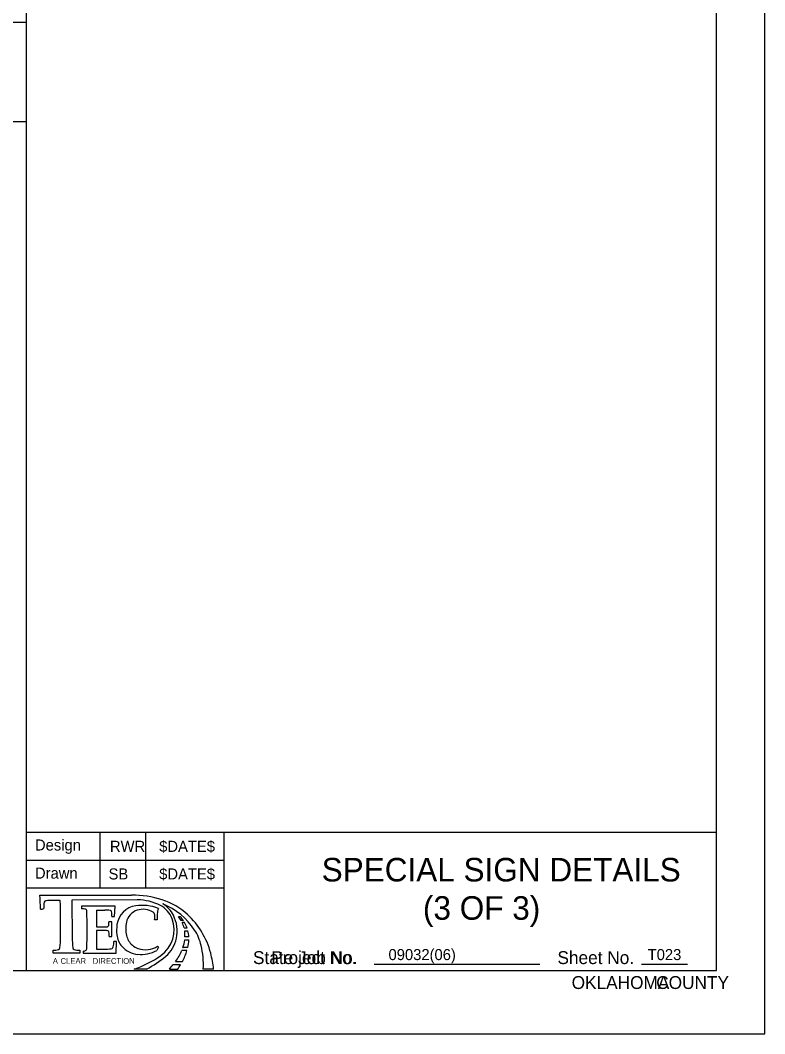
# Model space of a CAD drawing. Extents: x 2150010 to 2150174, y 145114 to 145224.
# Drawn here: x 2150135.1 to 2150174.1, y 145114.1 to 145167.1 of the extents above; entities that cross this region are included whole.
import ezdxf

# ---------------------------------------------------------------- set-up
doc = ezdxf.new("R2010")
doc.units = 0
for name, color, linetype in [('BORDER', 7, 'Continuous'), ('DATE', 7, 'Continuous'), ('Level 1', 7, 'Continuous'), ('PDF', 7, 'Continuous'), ('project no', 7, 'Continuous'), ('state job no', 7, 'Continuous'), ('TEC LOGO', 7, 'Continuous'), ('TEXT', 7, 'Continuous')]:
    doc.layers.add(name, color=color, linetype=linetype)

msp = doc.modelspace()

# ---------------------------------------------------------------- linework, layer by layer
at = {"layer": 'BORDER'}
for p, q in [((2150171.536, 145117.388), (2150171.536, 145216.512)), ((2150171.536, 145124.606), (2150135.447, 145124.606)), ((2150135.447, 145124.606), (2150135.447, 145117.388)), ((2150139.297, 145124.606), (2150139.297, 145121.719)), ((2150141.703, 145121.719), (2150141.703, 145124.606)), ((2150145.8, 145117.359), (2150145.8, 145124.577)), ((2150135.447, 145123.162), (2150145.8, 145123.162)), ((2150135.447, 145121.719), (2150145.8, 145121.719)), ((2150153.637, 145117.729), (2150162.298, 145117.729)), ((2150167.618, 145117.729), (2150170.024, 145117.729)), ((2150017.557, 145117.388), (2150171.536, 145117.388)), ((2150171.536, 145117.388), (2150171.536, 145117.388)), ((2150010.458, 145114.088), (2150174.061, 145114.088))]:
    msp.add_line(p, q, dxfattribs=at)
at = {"layer": 'Level 1'}
for p, q in [((2150135.447, 145216.512), (2150135.447, 145124.606)), ((2150135.447, 145166.95), (2150017.557, 145166.95)), ((2150120.969, 145161.778), (2150135.447, 145161.778))]:
    msp.add_line(p, q, dxfattribs=at)
at = {"layer": 'PDF'}
msp.add_lwpolyline([(2150010.458, 145114.088), (2150174.061, 145114.088), (2150174.061, 145219.948), (2150010.458, 145219.948)], close=True, dxfattribs=at)
at = {"layer": 'TEC LOGO'}
for p, q in [((2150136.163, 145121.335), (2150140.955, 145121.335)), ((2150137.238, 145121.058), (2150136.905, 145121.056)), ((2150141.264, 145121.082), (2150137.847, 145121.062)), ((2150137.847, 145121.062), (2150137.86, 145119.111)), ((2150138.352, 145120.759), (2150138.349, 145120.611)), ((2150140.106, 145120.759), (2150138.352, 145120.759)), ((2150140.07, 145120.219), (2150140.106, 145120.759)), ((2150139.134, 145120.555), (2150139.56, 145120.552)), ((2150139.925, 145120.219), (2150140.07, 145120.219)), ((2150142.307, 145120.354), (2150142.3, 145120.043)), ((2150143.414, 145120.213), (2150143.504, 145120.213)), ((2150139.925, 145119.934), (2150139.778, 145119.934)), ((2150139.925, 145119.172), (2150139.925, 145119.934)), ((2150142.3, 145120.043), (2150142.168, 145120.048)), ((2150143.669, 145120.008), (2150143.554, 145120.008)), ((2150143.731, 145119.909), (2150143.606, 145119.909)), ((2150143.709, 145119.627), (2150143.862, 145119.627)), ((2150139.785, 145119.172), (2150139.925, 145119.172)), ((2150143.74, 145119.471), (2150143.909, 145119.471)), ((2150143.957, 145119.151), (2150143.755, 145119.151)), ((2150140.175, 145118.91), (2150140.043, 145118.91)), ((2150140.159, 145118.3), (2150140.175, 145118.91)), ((2150142.374, 145118.62), (2150142.288, 145118.435)), ((2150142.324, 145118.657), (2150142.374, 145118.62)), ((2150143.903, 145118.595), (2150143.65, 145118.595)), ((2150143.743, 145118.997), (2150143.958, 145118.997)), ((2150136.856, 145118.3), (2150136.856, 145118.452)), ((2150138.255, 145118.3), (2150136.856, 145118.3)), ((2150138.255, 145118.452), (2150138.255, 145118.3)), ((2150138.439, 145118.399), (2150138.43, 145118.3)), ((2150138.43, 145118.3), (2150140.159, 145118.3)), ((2150143.86, 145118.438), (2150143.591, 145118.438)), ((2150141.747, 145117.467), (2150141.099, 145117.467)), ((2150142.942, 145117.467), (2150143.375, 145117.467)), ((2150143.52, 145117.689), (2150143.126, 145117.689)), ((2150143.264, 145117.867), (2150143.623, 145117.867)), ((2150145.252, 145117.467), (2150144.714, 145117.467))]:
    msp.add_line(p, q, dxfattribs=at)
for centre, radius, start, end in [((2150129.713, 145120.639), 6.487, 359.663, 6.1563), ((2150140.955, 145116.038), 5.297, 72.2522, 90), ((2150142.861, 145120.639), 6.487, 178.5623, 180.1181), ((2150137.218, 145120.781), 0.843, 167.5337, 178.5623), ((2150136.49, 145120.942), 0.0962, 94.698, 167.5337), ((2150136.937, 145115.493), 5.563, 90.3367, 94.698), ((2150046.46, 145119.478), 90.791, 359.77628, 0.99712), ((2150141.338, 145119.635), 1.149, 97.9231, 172.0344), ((2150141.514, 145118.371), 2.426, 69.3982, 97.9231), ((2150141.28, 145118.51), 2.573, 62.4303, 90.3367), ((2150143.117, 145120.335), 0.81, 157.7575, 178.6366), ((2150141.873, 145119.647), 1.289, 20.6867, 62.4303), ((2150141.492, 145117.716), 3.535, 47.2839, 72.2522), ((2150141.269, 145117.57), 3.562, 32.9982, 68.0651), ((2150141.873, 145119.647), 1.426, 26.3065, 59.3722), ((2150136.235, 145120.976), 0.377, 264.6321, 291.5899), ((2150138.383, 145119.475), 1.137, 80.6874, 91.7186), ((2150138.555, 145120.525), 0.0722, 1.4011, 80.6874), ((2150097.794, 145119.528), 40.845, 358.5952, 1.4011), ((2150222.857, 145119.533), 83.729, 179.30064, 179.90313), ((2150139.538, 145117.558), 2.995, 83.8831, 89.5816), ((2150139.849, 145120.463), 0.0722, 5.4112, 83.8831), ((2150138.327, 145120.319), 1.601, 356.4205, 5.4112), ((2150141.512, 145119.746), 0.839, 107.7088, 167.9528), ((2150141.562, 145119.589), 1.004, 58.2676, 107.7088), ((2150141.997, 145120.293), 0.176, 2.4202, 58.2676), ((2150140.098, 145120.213), 2.077, 355.4457, 2.4202), ((2150141.537, 145119.52), 1.649, 305.1645, 20.6867), ((2150141.484, 145119.455), 1.86, 348.2376, 26.3065), ((2150142.22, 145119.245), 1.536, 29.7365, 39.0219), ((2150142.29, 145119.068), 1.669, 34.2695, 43.3207), ((2150141.052, 145117.24), 4.183, 14.7043, 47.2839), ((2150139.363, 145128.515), 8.844, 268.4788, 271.5206), ((2150139.572, 145120.641), 0.967, 271.5206, 277.9096), ((2150139.695, 145119.755), 0.0722, 277.9096, 349.9583), ((2150138.932, 145119.89), 0.847, 349.9583, 3.0005), ((2150142.345, 145119.494), 2.166, 172.0344, 186.3105), ((2150142.25, 145119.588), 1.594, 167.9528, 193.0838), ((2150142.22, 145119.245), 1.536, 14.3628, 25.5725), ((2150142.29, 145119.068), 1.669, 19.5618, 30.2542), ((2150132.45, 145119.143), 4.801, 353.2347, 359.7763), ((2150142.661, 145119.143), 4.801, 180.3775, 186.7653), ((2150139.362, 145110.642), 8.844, 88.4794, 91.5212), ((2150222.857, 145119.533), 83.729, 180.03409, 180.69936), ((2150139.571, 145118.517), 0.967, 81.2846, 88.4794), ((2150139.707, 145119.401), 0.0722, 5.6885, 81.2846), ((2150138.141, 145119.245), 1.646, 357.4607, 5.6885), ((2150141.269, 145119.375), 1.083, 186.3105, 221.5776), ((2150141.645, 145119.448), 0.973, 193.0838, 228.7889), ((2150141.651, 145119.42), 1.689, 310.5997, 348.2376), ((2150142.22, 145119.245), 1.536, 2.0409, 8.4283), ((2150141.804, 145119.231), 1.952, 357.6694, 2.0409), ((2150142.29, 145119.068), 1.669, 2.8667, 13.9687), ((2150142.049, 145119.055), 1.911, 2.8951, 2.9107), ((2150142.146, 145118.139), 2.517, 12.951, 32.9982), ((2150137.122, 145118.588), 0.0962, 287.8364, 353.2347), ((2150137.989, 145118.588), 0.0962, 186.7653, 252.1636), ((2150138.531, 145118.529), 0.0962, 303.0633, 358.5952), ((2150139.369, 145127.352), 8.844, 268.4788, 273.4332), ((2150139.893, 145118.62), 0.0962, 273.4332, 326.9687), ((2150139.753, 145118.711), 0.263, 326.9687, 342.6077), ((2150139.168, 145118.894), 0.876, 342.6077, 1.0782), ((2150141.404, 145119.495), 1.263, 221.5776, 264.5103), ((2150141.577, 145119.37), 0.87, 228.7889, 251.3711), ((2150141.691, 145119.707), 1.226, 251.3711, 301.0817), ((2150141.152, 145119.455), 2.643, 341.0109, 341.0487), ((2150141.804, 145119.231), 1.952, 341.0487, 353.1199), ((2150142.049, 145119.055), 1.911, 346.0491, 358.2376), ((2150140.843, 145119.355), 3.152, 346.0548, 346.0603), ((2150140.037, 145117.654), 4.681, 357.7052, 12.951), ((2150136.867, 145119.381), 0.929, 269.3409, 287.8364), ((2150138.244, 145119.381), 0.929, 252.1636, 270.6591), ((2150138.412, 145118.712), 0.314, 274.8598, 303.0633), ((2150139.346, 145122.63), 5.453, 288.7522, 305.1645), ((2150141.454, 145120.022), 1.792, 264.5103, 297.7193), ((2150139.464, 145121.971), 5.05, 296.8707, 310.5997), ((2150141.152, 145119.455), 2.643, 323.1081, 337.382), ((2150140.843, 145119.355), 3.152, 331.8459, 343.1036), ((2150139.621, 145116.864), 5.663, 6.1104, 14.7043), ((2150137.249, 145122.384), 7.522, 319.179, 321.3834), ((2150137.249, 145122.384), 7.522, 323.0973, 323.1081), ((2150137.725, 145121.305), 6.831, 325.8118, 328.04), ((2150140.843, 145119.355), 3.152, 327.9791, 328.0787)]:
    msp.add_arc(centre, radius, start, end, dxfattribs=at)

# ---------------------------------------------------------------- texts
at = {"layer": 'BORDER'}
for s, height, p in [('Design', 0.5774, (2150135.913, 145123.665)), ('RWR', 0.5774, (2150139.833, 145123.596)), ('Drawn', 0.5774, (2150135.913, 145122.195)), ('SB ', 0.5774, (2150139.76, 145122.152)), ('09032(06)      ', 0.57742, (2150154.394, 145117.937)), (' T023', 0.5774, (2150167.726, 145117.937)), ('Sheet No.', 0.6737, (2150163.225, 145117.729)), ('       OKLAHOMA', 0.67366, (2150162.216, 145116.426)), (' COUNTY', 0.6737, (2150168.138, 145116.426))]:
    msp.add_text(s, height=height, dxfattribs=at).set_placement(p)
at = {"layer": 'DATE'}
for p in [(2150142.406, 145123.595), (2150142.406, 145122.152)]:
    msp.add_text('$DATE$', height=0.5774, dxfattribs=at).set_placement(p)
at = {"layer": 'project no'}
msp.add_text('Project No.', height=0.67366, dxfattribs=at).set_placement((2150148.267, 145117.729))
at = {"layer": 'state job no'}
msp.add_text('State Job No.', height=0.67366, dxfattribs=at).set_placement((2150147.312, 145117.729))
at = {"layer": 'TEC LOGO'}
for s, height, p in [('A', 0.298, (2150136.847, 145117.742)), ('CLEAR', 0.2983, (2150137.254, 145117.742)), ('DIRECTION', 0.2983, (2150138.933, 145117.742))]:
    msp.add_text(s, height=height, dxfattribs=at).set_placement(p)
at = {"layer": 'TEXT'}
for s, p in [('SPECIAL SIGN DETAILS', (2150150.9, 145122.047)), ('(3 OF 3)', (2150156.194, 145120.045))]:
    msp.add_text(s, height=1.232, dxfattribs=at).set_placement(p)

doc.saveas('drawing.dxf')
